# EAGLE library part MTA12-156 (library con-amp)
AMP connector
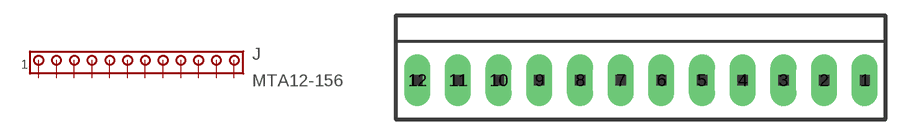
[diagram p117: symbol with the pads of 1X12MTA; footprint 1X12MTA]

Designator prefix J

## MTA12-156 (OC_FARNELL: unknown; OC_NEWARK: unknown)  [1X12MTA]
1  1  pas
2  2  pas
3  3  pas
4  4  pas
5  5  pas
6  6  pas
7  7  pas
8  8  pas
9  9  pas
10  10  pas
11  11  pas
12  12  pas

## Footprint 1X12MTA (pad centres in mm)
AMP MTA connector
drill 1.676 long: 1 21.793,0; 2 17.831,0; 3 13.868,0; 4 9.906,0; 5 5.944,0; 6 1.981,0; 7 -1.981,0; 8 -5.944,0; 9 -9.906,0; 10 -13.868,0; 11 -17.831,0; 12 -21.793,0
